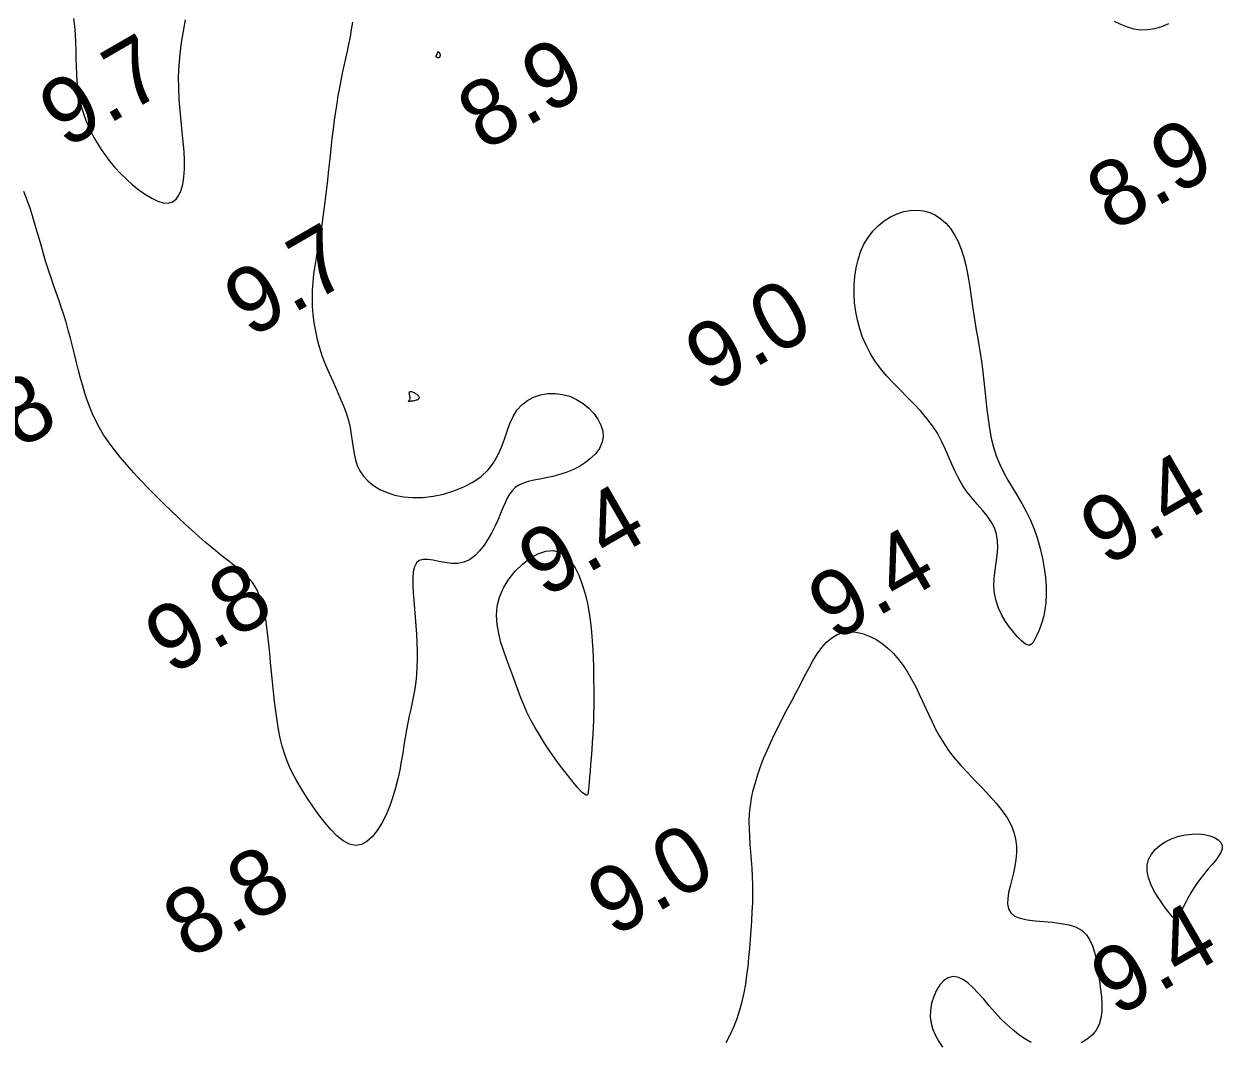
# Model space of a CAD drawing. Extents: x 3024098 to 3056816, y 418252 to 509144.
# Drawn here: x 3036811.1 to 3036902, y 419645.5 to 419722.7 of the extents above; entities that cross this region are included whole.
import ezdxf

# ---------------------------------------------------------------- set-up
doc = ezdxf.new("R2010")
doc.units = 0
doc.layers.add('V-CHAN-CONT-EL10', color=7, linetype='Continuous')
doc.layers.add('V-TOPO-SOUN-0911', color=7, linetype='Continuous')

msp = doc.modelspace()

# ---------------------------------------------------------------- linework, layer by layer
at = {"layer": 'V-CHAN-CONT-EL10'}
for points in [[(3036836.018, 419722.819), (3036835.934, 419722.267), (3036835.835, 419721.717), (3036835.725, 419721.168), (3036835.607, 419720.619), (3036835.486, 419720.071), (3036835.364, 419719.52), (3036835.245, 419718.967), (3036835.132, 419718.409), (3036835.025, 419717.843), (3036834.922, 419717.264), (3036834.824, 419716.667), (3036834.73, 419716.048), (3036834.64, 419715.401), (3036834.551, 419714.722), (3036834.465, 419714.006), (3036834.38, 419713.252), (3036834.296, 419712.466), (3036834.21, 419711.659), (3036834.122, 419710.841), (3036834.031, 419710.023), (3036833.935, 419709.214), (3036833.834, 419708.425), (3036833.726, 419707.665), (3036833.61, 419706.943), (3036833.491, 419706.254), (3036833.374, 419705.594), (3036833.262, 419704.956), (3036833.161, 419704.335), (3036833.075, 419703.724), (3036833.009, 419703.117), (3036832.968, 419702.509), (3036832.955, 419701.895), (3036832.971, 419701.275), (3036833.019, 419700.65), (3036833.097, 419700.02), (3036833.207, 419699.387), (3036833.349, 419698.753), (3036833.525, 419698.117), (3036833.734, 419697.481), (3036833.976, 419696.846), (3036834.241, 419696.214), (3036834.519, 419695.589), (3036834.798, 419694.971), (3036835.068, 419694.363), (3036835.318, 419693.767), (3036835.536, 419693.186), (3036835.713, 419692.623), (3036835.841, 419692.078), (3036835.932, 419691.552), (3036836.001, 419691.045), (3036836.066, 419690.557), (3036836.141, 419690.088), (3036836.242, 419689.637), (3036836.387, 419689.205), (3036836.59, 419688.791), (3036836.864, 419688.396), (3036837.209, 419688.026), (3036837.623, 419687.69), (3036838.101, 419687.394), (3036838.642, 419687.146), (3036839.241, 419686.954), (3036839.896, 419686.825), (3036840.603, 419686.766), (3036841.357, 419686.783), (3036842.139, 419686.876), (3036842.931, 419687.041), (3036843.71, 419687.276), (3036844.457, 419687.579), (3036845.152, 419687.946), (3036845.773, 419688.375), (3036846.301, 419688.863), (3036846.723, 419689.405), (3036847.054, 419689.988), (3036847.32, 419690.594), (3036847.543, 419691.207), (3036847.748, 419691.811), (3036847.959, 419692.389), (3036848.198, 419692.925), (3036848.491, 419693.402), (3036848.855, 419693.807), (3036849.283, 419694.136), (3036849.762, 419694.387), (3036850.281, 419694.56), (3036850.826, 419694.654), (3036851.385, 419694.668), (3036851.945, 419694.6), (3036852.494, 419694.45), (3036853.018, 419694.22), (3036853.507, 419693.918), (3036853.948, 419693.56), (3036854.329, 419693.156), (3036854.639, 419692.721), (3036854.867, 419692.266), (3036854.999, 419691.805), (3036855.026, 419691.351), (3036854.938, 419690.914), (3036854.747, 419690.5), (3036854.466, 419690.112), (3036854.11, 419689.754), (3036853.694, 419689.427), (3036853.232, 419689.137), (3036852.739, 419688.885), (3036852.229, 419688.676), (3036851.715, 419688.51), (3036851.205, 419688.379), (3036850.708, 419688.272), (3036850.229, 419688.178), (3036849.776, 419688.086), (3036849.357, 419687.985), (3036848.979, 419687.865), (3036848.648, 419687.714), (3036848.368, 419687.524), (3036848.134, 419687.294), (3036847.933, 419687.025), (3036847.755, 419686.716), (3036847.589, 419686.37), (3036847.425, 419685.987), (3036847.253, 419685.568), (3036847.062, 419685.114), (3036846.842, 419684.628), (3036846.593, 419684.127), (3036846.313, 419683.63), (3036846.003, 419683.155), (3036845.664, 419682.722), (3036845.294, 419682.349), (3036844.893, 419682.055), (3036844.462, 419681.86), (3036844.003, 419681.774), (3036843.527, 419681.776), (3036843.048, 419681.837), (3036842.58, 419681.927), (3036842.135, 419682.018), (3036841.729, 419682.08), (3036841.374, 419682.085), (3036841.084, 419682.002), (3036840.869, 419681.81), (3036840.722, 419681.515), (3036840.635, 419681.13), (3036840.596, 419680.67), (3036840.595, 419680.146), (3036840.623, 419679.574), (3036840.669, 419678.965), (3036840.723, 419678.333), (3036840.777, 419677.691), (3036840.826, 419677.044), (3036840.868, 419676.398), (3036840.899, 419675.756), (3036840.919, 419675.124), (3036840.923, 419674.506), (3036840.908, 419673.907), (3036840.874, 419673.331), (3036840.817, 419672.782), (3036840.741, 419672.254), (3036840.65, 419671.741), (3036840.548, 419671.235), (3036840.439, 419670.73), (3036840.328, 419670.219), (3036840.218, 419669.695), (3036840.114, 419669.151), (3036840.018, 419668.582), (3036839.926, 419667.989), (3036839.83, 419667.374), (3036839.726, 419666.74), (3036839.606, 419666.089), (3036839.464, 419665.425), (3036839.294, 419664.75), (3036839.089, 419664.065), (3036838.846, 419663.379), (3036838.564, 419662.709), (3036838.248, 419662.081), (3036837.901, 419661.517), (3036837.524, 419661.04), (3036837.121, 419660.675), (3036836.696, 419660.445), (3036836.251, 419660.373), (3036835.79, 419660.474), (3036835.319, 419660.728), (3036834.844, 419661.108), (3036834.374, 419661.583), (3036833.913, 419662.127), (3036833.471, 419662.71), (3036833.052, 419663.304), (3036832.665, 419663.881), (3036832.314, 419664.419), (3036831.999, 419664.923), (3036831.716, 419665.405), (3036831.463, 419665.878), (3036831.237, 419666.354), (3036831.035, 419666.845), (3036830.855, 419667.363), (3036830.695, 419667.92), (3036830.55, 419668.524), (3036830.421, 419669.172), (3036830.305, 419669.855), (3036830.201, 419670.566), (3036830.107, 419671.296), (3036830.022, 419672.038), (3036829.945, 419672.784), (3036829.874, 419673.525), (3036829.807, 419674.255), (3036829.742, 419674.968), (3036829.676, 419675.657), (3036829.606, 419676.318), (3036829.529, 419676.945), (3036829.443, 419677.533), (3036829.344, 419678.076), (3036829.231, 419678.57), (3036829.1, 419679.009), (3036828.953, 419679.398), (3036828.791, 419679.743), (3036828.617, 419680.048), (3036828.431, 419680.319), (3036828.236, 419680.562), (3036828.034, 419680.782), (3036827.826, 419680.984), (3036827.612, 419681.174), (3036827.39, 419681.359), (3036827.156, 419681.545), (3036826.905, 419681.738), (3036826.633, 419681.946), (3036826.336, 419682.175), (3036826.009, 419682.432), (3036825.649, 419682.722), (3036825.252, 419683.053), (3036824.822, 419683.422), (3036824.36, 419683.826), (3036823.871, 419684.264), (3036823.358, 419684.734), (3036822.825, 419685.231), (3036822.275, 419685.755), (3036821.711, 419686.302), (3036821.138, 419686.869), (3036820.563, 419687.452), (3036819.994, 419688.046), (3036819.439, 419688.645), (3036818.906, 419689.244), (3036818.403, 419689.837), (3036817.937, 419690.42), (3036817.518, 419690.988), (3036817.15, 419691.536), (3036816.83, 419692.069), (3036816.551, 419692.593), (3036816.308, 419693.111), (3036816.094, 419693.63), (3036815.903, 419694.156), (3036815.729, 419694.694), (3036815.566, 419695.248), (3036815.408, 419695.824), (3036815.253, 419696.417), (3036815.1, 419697.023), (3036814.946, 419697.636), (3036814.791, 419698.252), (3036814.632, 419698.864), (3036814.468, 419699.47), (3036814.297, 419700.062), (3036814.119, 419700.638), (3036813.935, 419701.202), (3036813.745, 419701.759), (3036813.551, 419702.315), (3036813.356, 419702.876), (3036813.161, 419703.446), (3036812.967, 419704.031), (3036812.775, 419704.637), (3036812.587, 419705.268), (3036812.4, 419705.921), (3036812.211, 419706.589), (3036812.015, 419707.267), (3036811.81, 419707.952), (3036811.591, 419708.637), (3036811.356, 419709.316), (3036811.101, 419709.986)], [(3036814.873, 419723.102), (3036814.946, 419722.514), (3036814.993, 419721.909), (3036815.02, 419721.293), (3036815.034, 419720.675), (3036815.045, 419720.064), (3036815.058, 419719.466), (3036815.082, 419718.89), (3036815.122, 419718.342), (3036815.182, 419717.82), (3036815.261, 419717.32), (3036815.361, 419716.837), (3036815.48, 419716.368), (3036815.622, 419715.908), (3036815.785, 419715.454), (3036815.971, 419715.001), (3036816.18, 419714.546), (3036816.413, 419714.09), (3036816.673, 419713.632), (3036816.961, 419713.174), (3036817.279, 419712.717), (3036817.627, 419712.262), (3036818.008, 419711.809), (3036818.423, 419711.359), (3036818.872, 419710.917), (3036819.344, 419710.492), (3036819.83, 419710.1), (3036820.317, 419709.754), (3036820.794, 419709.468), (3036821.249, 419709.256), (3036821.672, 419709.133), (3036822.05, 419709.111), (3036822.374, 419709.202), (3036822.645, 419709.4), (3036822.865, 419709.696), (3036823.037, 419710.08), (3036823.162, 419710.545), (3036823.243, 419711.08), (3036823.283, 419711.677), (3036823.284, 419712.326), (3036823.25, 419713.02), (3036823.189, 419713.752), (3036823.112, 419714.518), (3036823.029, 419715.313), (3036822.951, 419716.132), (3036822.886, 419716.97), (3036822.846, 419717.821), (3036822.84, 419718.682), (3036822.877, 419719.548), (3036822.953, 419720.416), (3036823.064, 419721.284), (3036823.203, 419722.152), (3036823.367, 419723.017)], [(3036897.901, 419722.699), (3036897.384, 419722.479), (3036896.848, 419722.323), (3036896.309, 419722.238), (3036895.781, 419722.23), (3036895.274, 419722.302), (3036894.784, 419722.446), (3036894.301, 419722.646), (3036893.816, 419722.892)], [(3036864.358, 419645.437), (3036864.666, 419646.017), (3036864.947, 419646.631), (3036865.194, 419647.265), (3036865.403, 419647.907), (3036865.578, 419648.556), (3036865.722, 419649.211), (3036865.84, 419649.873), (3036865.938, 419650.541), (3036866.019, 419651.214), (3036866.088, 419651.894), (3036866.149, 419652.579), (3036866.207, 419653.269), (3036866.261, 419653.962), (3036866.307, 419654.655), (3036866.345, 419655.345), (3036866.372, 419656.029), (3036866.387, 419656.704), (3036866.386, 419657.368), (3036866.369, 419658.018), (3036866.335, 419658.651), (3036866.288, 419659.27), (3036866.237, 419659.876), (3036866.187, 419660.473), (3036866.146, 419661.063), (3036866.119, 419661.647), (3036866.115, 419662.229), (3036866.14, 419662.811), (3036866.199, 419663.395), (3036866.292, 419663.981), (3036866.417, 419664.571), (3036866.573, 419665.165), (3036866.756, 419665.763), (3036866.967, 419666.366), (3036867.202, 419666.973), (3036867.461, 419667.587), (3036867.74, 419668.206), (3036868.037, 419668.831), (3036868.348, 419669.458), (3036868.67, 419670.087), (3036868.998, 419670.717), (3036869.329, 419671.346), (3036869.659, 419671.973), (3036869.986, 419672.596), (3036870.306, 419673.212), (3036870.623, 419673.811), (3036870.943, 419674.382), (3036871.272, 419674.911), (3036871.615, 419675.388), (3036871.977, 419675.8), (3036872.364, 419676.135), (3036872.78, 419676.383), (3036873.23, 419676.533), (3036873.707, 419676.589), (3036874.202, 419676.559), (3036874.705, 419676.449), (3036875.209, 419676.267), (3036875.704, 419676.018), (3036876.182, 419675.711), (3036876.633, 419675.351), (3036877.05, 419674.946), (3036877.436, 419674.501), (3036877.792, 419674.024), (3036878.121, 419673.521), (3036878.428, 419672.997), (3036878.714, 419672.46), (3036878.983, 419671.915), (3036879.237, 419671.369), (3036879.481, 419670.827), (3036879.723, 419670.289), (3036879.973, 419669.752), (3036880.24, 419669.214), (3036880.532, 419668.675), (3036880.86, 419668.132), (3036881.234, 419667.582), (3036881.661, 419667.026), (3036882.147, 419666.46), (3036882.677, 419665.888), (3036883.231, 419665.312), (3036883.79, 419664.735), (3036884.333, 419664.159), (3036884.842, 419663.587), (3036885.297, 419663.022), (3036885.677, 419662.467), (3036885.968, 419661.923), (3036886.174, 419661.39), (3036886.305, 419660.865), (3036886.37, 419660.347), (3036886.377, 419659.835), (3036886.336, 419659.326), (3036886.257, 419658.818), (3036886.148, 419658.311), (3036886.021, 419657.803), (3036885.893, 419657.304), (3036885.784, 419656.822), (3036885.715, 419656.368), (3036885.706, 419655.952), (3036885.776, 419655.583), (3036885.946, 419655.272), (3036886.236, 419655.029), (3036886.657, 419654.858), (3036887.186, 419654.744), (3036887.793, 419654.669), (3036888.447, 419654.612), (3036889.117, 419654.553), (3036889.773, 419654.474), (3036890.383, 419654.355), (3036890.916, 419654.175), (3036891.349, 419653.921), (3036891.69, 419653.595), (3036891.951, 419653.207), (3036892.149, 419652.765), (3036892.297, 419652.278), (3036892.409, 419651.755), (3036892.5, 419651.204), (3036892.585, 419650.635), (3036892.673, 419650.054), (3036892.755, 419649.472), (3036892.82, 419648.895), (3036892.854, 419648.332), (3036892.845, 419647.791), (3036892.779, 419647.279), (3036892.644, 419646.805), (3036892.427, 419646.378), (3036892.119, 419646.003), (3036891.732, 419645.684), (3036891.279, 419645.425)], [(3036887.503, 419645.449), (3036887.008, 419645.719), (3036886.529, 419646.044), (3036886.065, 419646.415), (3036885.614, 419646.825), (3036885.172, 419647.27), (3036884.739, 419647.74), (3036884.312, 419648.229), (3036883.892, 419648.716), (3036883.479, 419649.181), (3036883.074, 419649.604), (3036882.678, 419649.963), (3036882.292, 419650.237), (3036881.916, 419650.406), (3036881.552, 419650.449), (3036881.201, 419650.352), (3036880.871, 419650.13), (3036880.572, 419649.804), (3036880.312, 419649.396), (3036880.099, 419648.929), (3036879.944, 419648.424), (3036879.855, 419647.902), (3036879.841, 419647.386), (3036879.907, 419646.893), (3036880.045, 419646.421), (3036880.243, 419645.966), (3036880.487, 419645.519), (3036880.767, 419645.077)]]:
    msp.add_lwpolyline(points, dxfattribs=at)
for points in [[(3036842.369, 419720.267), (3036842.375, 419720.282), (3036842.383, 419720.298), (3036842.392, 419720.316), (3036842.402, 419720.335), (3036842.413, 419720.356), (3036842.424, 419720.379), (3036842.434, 419720.405), (3036842.444, 419720.432), (3036842.454, 419720.46), (3036842.463, 419720.488), (3036842.473, 419720.515), (3036842.483, 419720.539), (3036842.494, 419720.558), (3036842.506, 419720.572), (3036842.519, 419720.58), (3036842.534, 419720.58), (3036842.55, 419720.574), (3036842.567, 419720.562), (3036842.583, 419720.545), (3036842.6, 419720.526), (3036842.615, 419720.505), (3036842.629, 419720.483), (3036842.64, 419720.462), (3036842.649, 419720.442), (3036842.656, 419720.424), (3036842.661, 419720.406), (3036842.664, 419720.389), (3036842.665, 419720.372), (3036842.666, 419720.355), (3036842.665, 419720.336), (3036842.663, 419720.316), (3036842.661, 419720.294), (3036842.657, 419720.272), (3036842.653, 419720.248), (3036842.648, 419720.225), (3036842.641, 419720.203), (3036842.632, 419720.183), (3036842.622, 419720.165), (3036842.609, 419720.15), (3036842.594, 419720.138), (3036842.578, 419720.131), (3036842.56, 419720.126), (3036842.541, 419720.123), (3036842.522, 419720.123), (3036842.503, 419720.125), (3036842.486, 419720.127), (3036842.47, 419720.131), (3036842.456, 419720.135), (3036842.444, 419720.14), (3036842.433, 419720.145), (3036842.424, 419720.151), (3036842.416, 419720.157), (3036842.408, 419720.163), (3036842.401, 419720.17), (3036842.394, 419720.177), (3036842.387, 419720.184), (3036842.381, 419720.192), (3036842.374, 419720.2), (3036842.369, 419720.209), (3036842.365, 419720.219), (3036842.363, 419720.23), (3036842.363, 419720.241), (3036842.364, 419720.253)], [(3036884.666, 419680.085), (3036884.688, 419680.669), (3036884.75, 419681.253), (3036884.831, 419681.832), (3036884.906, 419682.401), (3036884.954, 419682.956), (3036884.949, 419683.49), (3036884.871, 419684), (3036884.701, 419684.482), (3036884.452, 419684.942), (3036884.142, 419685.387), (3036883.788, 419685.826), (3036883.408, 419686.266), (3036883.022, 419686.715), (3036882.646, 419687.181), (3036882.3, 419687.671), (3036881.995, 419688.191), (3036881.723, 419688.737), (3036881.47, 419689.303), (3036881.223, 419689.883), (3036880.967, 419690.471), (3036880.69, 419691.06), (3036880.376, 419691.645), (3036880.012, 419692.219), (3036879.589, 419692.778), (3036879.116, 419693.325), (3036878.609, 419693.863), (3036878.082, 419694.396), (3036877.549, 419694.93), (3036877.024, 419695.467), (3036876.523, 419696.012), (3036876.059, 419696.569), (3036875.645, 419697.142), (3036875.282, 419697.73), (3036874.969, 419698.333), (3036874.704, 419698.948), (3036874.486, 419699.577), (3036874.315, 419700.217), (3036874.188, 419700.868), (3036874.104, 419701.529), (3036874.063, 419702.198), (3036874.067, 419702.869), (3036874.116, 419703.533), (3036874.214, 419704.184), (3036874.361, 419704.814), (3036874.56, 419705.416), (3036874.813, 419705.981), (3036875.122, 419706.504), (3036875.486, 419706.976), (3036875.898, 419707.394), (3036876.349, 419707.754), (3036876.829, 419708.054), (3036877.329, 419708.289), (3036877.838, 419708.457), (3036878.348, 419708.554), (3036878.849, 419708.577), (3036879.333, 419708.523), (3036879.795, 419708.394), (3036880.233, 419708.193), (3036880.644, 419707.921), (3036881.025, 419707.582), (3036881.372, 419707.178), (3036881.684, 419706.711), (3036881.957, 419706.184), (3036882.189, 419705.6), (3036882.385, 419704.97), (3036882.551, 419704.302), (3036882.692, 419703.609), (3036882.814, 419702.899), (3036882.923, 419702.185), (3036883.024, 419701.477), (3036883.124, 419700.784), (3036883.227, 419700.115), (3036883.332, 419699.466), (3036883.437, 419698.83), (3036883.541, 419698.2), (3036883.643, 419697.57), (3036883.739, 419696.932), (3036883.829, 419696.281), (3036883.911, 419695.608), (3036883.985, 419694.91), (3036884.056, 419694.192), (3036884.132, 419693.463), (3036884.22, 419692.73), (3036884.328, 419692.001), (3036884.464, 419691.286), (3036884.634, 419690.59), (3036884.847, 419689.924), (3036885.106, 419689.291), (3036885.405, 419688.685), (3036885.733, 419688.096), (3036886.078, 419687.514), (3036886.432, 419686.929), (3036886.782, 419686.331), (3036887.119, 419685.71), (3036887.433, 419685.057), (3036887.714, 419684.364), (3036887.959, 419683.641), (3036888.168, 419682.901), (3036888.34, 419682.156), (3036888.473, 419681.418), (3036888.567, 419680.701), (3036888.62, 419680.017), (3036888.632, 419679.379), (3036888.603, 419678.796), (3036888.539, 419678.269), (3036888.446, 419677.795), (3036888.333, 419677.371), (3036888.207, 419676.996), (3036888.075, 419676.666), (3036887.944, 419676.379), (3036887.821, 419676.132), (3036887.711, 419675.924), (3036887.61, 419675.759), (3036887.508, 419675.642), (3036887.399, 419675.577), (3036887.273, 419675.568), (3036887.124, 419675.622), (3036886.944, 419675.743), (3036886.724, 419675.935), (3036886.461, 419676.201), (3036886.167, 419676.535), (3036885.86, 419676.929), (3036885.556, 419677.375), (3036885.272, 419677.863), (3036885.025, 419678.387), (3036884.831, 419678.937), (3036884.708, 419679.505)], [(3036840.385, 419694.82), (3036840.43, 419694.827), (3036840.487, 419694.819), (3036840.551, 419694.799), (3036840.621, 419694.771), (3036840.692, 419694.734), (3036840.763, 419694.693), (3036840.83, 419694.65), (3036840.89, 419694.606), (3036840.943, 419694.562), (3036840.989, 419694.519), (3036841.025, 419694.476), (3036841.053, 419694.434), (3036841.071, 419694.394), (3036841.078, 419694.355), (3036841.074, 419694.318), (3036841.059, 419694.283), (3036841.033, 419694.251), (3036840.997, 419694.221), (3036840.953, 419694.194), (3036840.901, 419694.169), (3036840.843, 419694.147), (3036840.779, 419694.127), (3036840.711, 419694.11), (3036840.639, 419694.096), (3036840.567, 419694.085), (3036840.496, 419694.076), (3036840.43, 419694.07), (3036840.371, 419694.066), (3036840.321, 419694.065), (3036840.283, 419694.066), (3036840.26, 419694.069), (3036840.254, 419694.074), (3036840.261, 419694.082), (3036840.279, 419694.095), (3036840.302, 419694.114), (3036840.328, 419694.139), (3036840.353, 419694.173), (3036840.374, 419694.216), (3036840.385, 419694.27), (3036840.386, 419694.334), (3036840.378, 419694.407), (3036840.365, 419694.484), (3036840.351, 419694.561), (3036840.339, 419694.635), (3036840.333, 419694.702), (3036840.336, 419694.757), (3036840.353, 419694.798)], [(3036849.528, 419669.939), (3036849.254, 419670.499), (3036849.011, 419671.047), (3036848.788, 419671.59), (3036848.58, 419672.135), (3036848.377, 419672.689), (3036848.171, 419673.258), (3036847.954, 419673.849), (3036847.724, 419674.467), (3036847.493, 419675.109), (3036847.281, 419675.771), (3036847.108, 419676.449), (3036846.991, 419677.138), (3036846.95, 419677.833), (3036847.004, 419678.532), (3036847.172, 419679.228), (3036847.466, 419679.916), (3036847.868, 419680.576), (3036848.355, 419681.187), (3036848.904, 419681.728), (3036849.489, 419682.177), (3036850.088, 419682.514), (3036850.677, 419682.716), (3036851.23, 419682.763), (3036851.73, 419682.641), (3036852.174, 419682.365), (3036852.565, 419681.956), (3036852.907, 419681.439), (3036853.202, 419680.836), (3036853.452, 419680.168), (3036853.662, 419679.459), (3036853.834, 419678.732), (3036853.97, 419678.005), (3036854.076, 419677.286), (3036854.154, 419676.58), (3036854.211, 419675.891), (3036854.249, 419675.222), (3036854.274, 419674.579), (3036854.289, 419673.965), (3036854.299, 419673.386), (3036854.307, 419672.842), (3036854.314, 419672.328), (3036854.318, 419671.834), (3036854.318, 419671.351), (3036854.314, 419670.87), (3036854.305, 419670.382), (3036854.29, 419669.878), (3036854.267, 419669.35), (3036854.238, 419668.791), (3036854.202, 419668.213), (3036854.163, 419667.631), (3036854.121, 419667.06), (3036854.078, 419666.513), (3036854.037, 419666.006), (3036854, 419665.554), (3036853.967, 419665.172), (3036853.941, 419664.869), (3036853.92, 419664.64), (3036853.902, 419664.474), (3036853.887, 419664.361), (3036853.873, 419664.289), (3036853.857, 419664.247), (3036853.838, 419664.227), (3036853.816, 419664.215), (3036853.786, 419664.207), (3036853.744, 419664.209), (3036853.683, 419664.231), (3036853.597, 419664.287), (3036853.478, 419664.385), (3036853.32, 419664.538), (3036853.117, 419664.757), (3036852.863, 419665.053), (3036852.552, 419665.432), (3036852.197, 419665.885), (3036851.809, 419666.397), (3036851.401, 419666.955), (3036850.987, 419667.545), (3036850.581, 419668.152), (3036850.194, 419668.762), (3036849.84, 419669.361)], [(3036896.39, 419659.316), (3036896.604, 419659.717), (3036896.906, 419660.079), (3036897.281, 419660.4), (3036897.713, 419660.676), (3036898.185, 419660.903), (3036898.683, 419661.077), (3036899.191, 419661.193), (3036899.692, 419661.251), (3036900.175, 419661.253), (3036900.626, 419661.204), (3036901.033, 419661.11), (3036901.383, 419660.975), (3036901.664, 419660.804), (3036901.862, 419660.603), (3036901.965, 419660.375), (3036901.966, 419660.127), (3036901.875, 419659.858), (3036901.709, 419659.571), (3036901.485, 419659.266), (3036901.218, 419658.944), (3036900.926, 419658.606), (3036900.624, 419658.254), (3036900.329, 419657.887), (3036900.054, 419657.509), (3036899.802, 419657.126), (3036899.574, 419656.747), (3036899.368, 419656.379), (3036899.185, 419656.032), (3036899.024, 419655.714), (3036898.886, 419655.432), (3036898.77, 419655.196), (3036898.674, 419655.012), (3036898.592, 419654.884), (3036898.513, 419654.813), (3036898.43, 419654.803), (3036898.331, 419654.855), (3036898.209, 419654.971), (3036898.055, 419655.153), (3036897.858, 419655.404), (3036897.615, 419655.723), (3036897.343, 419656.101), (3036897.062, 419656.524), (3036896.795, 419656.98), (3036896.561, 419657.456), (3036896.383, 419657.941), (3036896.282, 419658.42), (3036896.279, 419658.882)]]:
    msp.add_lwpolyline(points, close=True, dxfattribs=at)

# ---------------------------------------------------------------- texts
at = {"layer": 'V-TOPO-SOUN-0911'}
for s, p in [('9.7', (3036814.247, 419713.171)), ('8.9', (3036845.977, 419712.971)), ('8.9', (3036893.677, 419706.871)), ('9.7', (3036828.257, 419698.801)), ('9.0', (3036863.225, 419694.661)), ('8.8', (3036805.917, 419687.611)), ('9.4', (3036893.187, 419681.481)), ('9.4', (3036850.567, 419679.081)), ('9.4', (3036872.547, 419675.801)), ('9.8', (3036822.257, 419673.241)), ('9.0', (3036855.805, 419653.361)), ('8.8', (3036823.637, 419651.691)), ('9.4', (3036893.977, 419647.321))]:
    msp.add_text(s, height=5, rotation=30, dxfattribs=at).set_placement(p)

doc.saveas('drawing.dxf')
